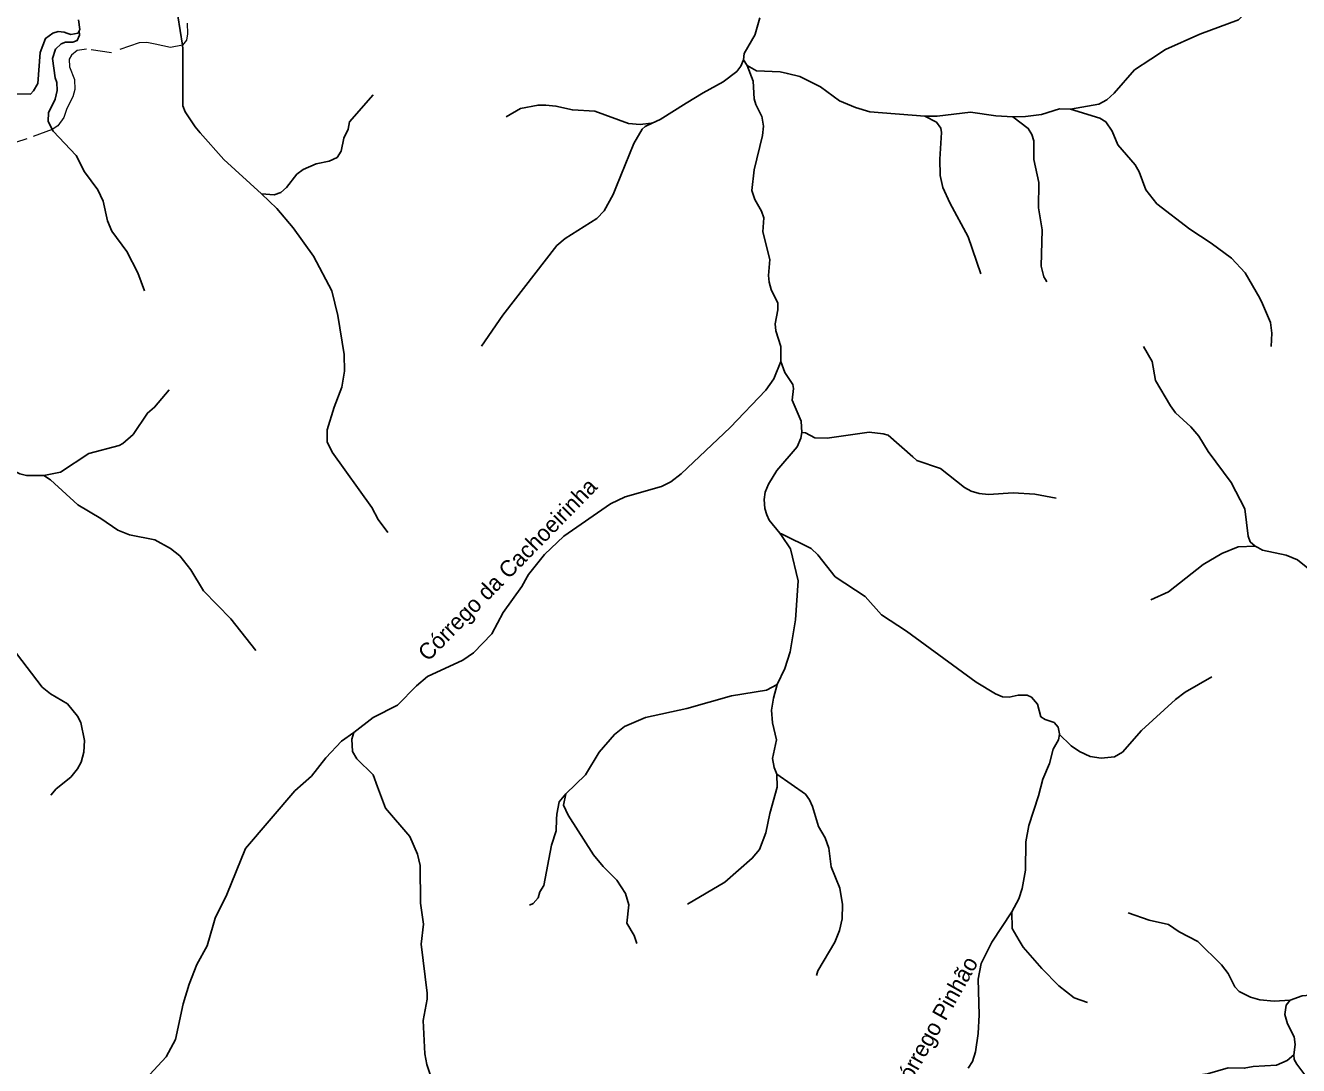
# Model space of a CAD drawing. Extents: x 473.9 to 500, y 7733.1 to 7760.8.
# Drawn here: x 481.48 to 487.72, y 7748.41 to 7753.5 of the extents above; entities that cross this region are included whole.
import ezdxf
from ezdxf.enums import TextEntityAlignment as Align

# ---------------------------------------------------------------- set-up
doc = ezdxf.new("R2010")
doc.units = 0
doc.header["$LTSCALE"] = 0.032
doc.linetypes.add('SHORT_DASHED', pattern=[2.7, 1.5, -1.2])
doc.layers.add('21', color=7, linetype='SHORT_DASHED', lineweight=13)
doc.layers.add('7', color=7, linetype='Continuous', lineweight=25)
doc.layers.add('61', color=7, linetype='Continuous')

msp = doc.modelspace()

# ---------------------------------------------------------------- linework, layer by layer
at = {"layer": '21'}
for points in [[(482.2765, 7753.5139), (482.2782, 7753.4628), (482.2731, 7753.4304), (482.2522, 7753.407)], [(482.2522, 7753.407), (482.1948, 7753.3947), (482.1184, 7753.4115), (482.078, 7753.4191), (482.0406, 7753.418), (481.9044, 7753.3699), (481.7824, 7753.3874), (481.7363, 7753.3808), (481.7091, 7753.3579), (481.6973, 7753.3383), (481.6989, 7753.2997), (481.7235, 7753.2383), (481.7251, 7753.1887), (481.7159, 7753.1539), (481.6852, 7753.0955), (481.6713, 7753.0526), (481.6415, 7753.0116), (481.6148, 7752.994)], [(481.6148, 7752.994), (481.4906, 7752.9475), (481.4339, 7752.9294), (481.3738, 7752.8971), (481.3009, 7752.8454), (481.2522, 7752.8327), (481.1964, 7752.827), (481.1559, 7752.8103), (481.1272, 7752.7832), (481.0901, 7752.6822), (481.079, 7752.6676), (481.0582, 7752.6403), (481.0361, 7752.6262), (480.9428, 7752.5927), (480.9205, 7752.577), (480.9027, 7752.5377), (480.9186, 7752.4147), (480.9083, 7752.277), (480.8936, 7752.2196), (480.8676, 7752.1741), (480.848, 7752.162), (480.7931, 7752.1553)]]:
    msp.add_lwpolyline(points, dxfattribs=at)
at = {"layer": '7'}
msp.add_line((485.0216, 7753.3077), (485.0036, 7753.3356), dxfattribs=at)
for points in [[(483.1296, 7754.8539), (483.1149, 7754.7823), (483.0796, 7754.7372), (482.9905, 7754.6958), (482.7757, 7754.5657), (482.7324, 7754.5381), (482.6795, 7754.4882), (482.5869, 7754.2753), (482.4227, 7754.0463), (482.3873, 7753.9719), (482.369, 7753.9149), (482.2405, 7753.7174), (482.2311, 7753.6852), (482.2306, 7753.551), (482.2522, 7753.407)], [(487.671, 7753.9257), (487.6551, 7753.8617), (487.6509, 7753.8037), (487.642, 7753.7843), (487.5676, 7753.7056), (487.4959, 7753.599), (487.4299, 7753.5316), (487.2405, 7753.4613), (487.0722, 7753.386), (486.9996, 7753.3382), (486.9192, 7753.2853), (486.8205, 7753.1711), (486.7836, 7753.1389), (486.7449, 7753.1182), (486.6061, 7753.0928)], [(481.7437, 7753.5302), (481.7497, 7753.4837), (481.746, 7753.4764)], [(485.0036, 7753.3356), (485.0068, 7753.3652), (485.0595, 7753.459), (485.0603, 7753.4604), (485.0828, 7753.5407)], [(481.746, 7753.4764), (481.7407, 7753.4658), (481.7054, 7753.4592), (481.6865, 7753.466), (481.6725, 7753.471), (481.6436, 7753.4739), (481.6173, 7753.466), (481.5815, 7753.44), (481.5557, 7753.3713), (481.5433, 7753.219), (481.5233, 7753.1829), (481.5076, 7753.1672), (481.4409, 7753.1674)], [(481.6148, 7752.994), (481.5947, 7753.0345), (481.5968, 7753.0748), (481.6282, 7753.1414), (481.6389, 7753.1844), (481.6374, 7753.2234), (481.629, 7753.2458), (481.6152, 7753.3414), (481.6298, 7753.3864), (481.6587, 7753.4139), (481.6798, 7753.421), (481.7096, 7753.4208), (481.7147, 7753.4208), (481.737, 7753.4298), (481.7482, 7753.4556), (481.746, 7753.4764)], [(482.2522, 7753.407), (482.255, 7753.3884), (482.2551, 7753.1095), (482.2654, 7753.0805), (482.3143, 7753.0061), (482.3401, 7752.9771), (482.4562, 7752.8464), (482.6401, 7752.6788)], [(484.5556, 7753.0242), (484.5937, 7753.0424), (484.7214, 7753.1218), (484.8049, 7753.1737), (484.9027, 7753.2266), (484.9696, 7753.2783), (484.9898, 7753.3038), (485.0036, 7753.3356)], [(485.8921, 7753.0585), (485.6228, 7753.0797), (485.5516, 7753.1004), (485.4736, 7753.1333), (485.3808, 7753.2018), (485.2787, 7753.2524), (485.2185, 7753.2671), (485.1819, 7753.2761), (485.0673, 7753.2806), (485.0216, 7753.3077)], [(485.1864, 7751.8564), (485.1863, 7751.9295), (485.1615, 7752.0074), (485.1583, 7752.0403), (485.1719, 7752.1091), (485.1719, 7752.1417), (485.1389, 7752.2101), (485.129, 7752.2452), (485.1254, 7752.2783), (485.1326, 7752.357), (485.0974, 7752.4917), (485.1029, 7752.5612), (485.0914, 7752.5937), (485.0583, 7752.6502), (485.0436, 7752.6937), (485.0557, 7752.7955), (485.0965, 7752.9634), (485.1013, 7753.009), (485.0922, 7753.0591), (485.0915, 7753.0605), (485.0639, 7753.1152), (485.0557, 7753.1443), (485.0501, 7753.2309), (485.0216, 7753.3077)], [(483.1871, 7753.1635), (483.0722, 7753.0316), (483.0649, 7752.9945), (483.0442, 7752.9514), (483.0314, 7752.8873), (483.0107, 7752.8557), (482.9726, 7752.8386), (482.9089, 7752.8246), (482.8444, 7752.7979), (482.8141, 7752.7745), (482.7632, 7752.7097), (482.7347, 7752.6846), (482.7021, 7752.6738), (482.6401, 7752.6788)], [(483.8393, 7753.0557), (483.9099, 7753.0969), (483.9961, 7753.1134), (484.034, 7753.1134), (484.0836, 7753.1085), (484.1642, 7753.0892), (484.2735, 7753.0838), (484.439, 7753.0225), (484.4961, 7753.018), (484.5511, 7753.0237), (484.5556, 7753.0242)], [(486.3227, 7753.0558), (486.2392, 7753.0597), (486.115, 7753.0789), (485.9517, 7753.0595), (485.8921, 7753.0585)], [(486.6061, 7753.0928), (486.5523, 7753.0944), (486.4633, 7753.0663), (486.3847, 7753.0564), (486.3227, 7753.0558)], [(487.59, 7751.9305), (487.5933, 7751.9947), (487.5854, 7752.0473), (487.5463, 7752.1393), (487.5346, 7752.1668), (487.4623, 7752.2902), (487.3944, 7752.3629), (487.2956, 7752.4371), (487.1902, 7752.5049), (487.0291, 7752.6289), (486.9749, 7752.6975), (486.9417, 7752.7864), (486.9233, 7752.8201), (486.8384, 7752.9179), (486.8107, 7752.9859), (486.7786, 7753.0315), (486.7492, 7753.0491), (486.6061, 7753.0928)], [(483.7182, 7751.9313), (483.8227, 7752.084), (484.0887, 7752.4254), (484.129, 7752.4596), (484.2833, 7752.5568), (484.3205, 7752.5949), (484.3644, 7752.6748), (484.3811, 7752.7163), (484.465, 7752.9255), (484.5061, 7752.9944), (484.5212, 7753.0077), (484.5556, 7753.0242)], [(486.1657, 7752.2854), (486.1041, 7752.4668), (486.0143, 7752.6344), (485.9808, 7752.7089), (485.9673, 7752.7675), (485.9656, 7752.8476), (485.9736, 7752.9792), (485.9694, 7752.9994), (485.9495, 7753.0293), (485.8921, 7753.0585)], [(486.4905, 7752.2461), (486.4838, 7752.2578), (486.4756, 7752.272), (486.462, 7752.3234), (486.4675, 7752.5016), (486.4484, 7752.61), (486.4499, 7752.7341), (486.4259, 7752.8461), (486.4256, 7752.9374), (486.4165, 7752.9692), (486.3988, 7752.9985), (486.3227, 7753.0558)], [(482.0667, 7752.2033), (482.0335, 7752.2905), (481.9807, 7752.3951), (481.9072, 7752.4949), (481.8859, 7752.5456), (481.8644, 7752.6414), (481.8387, 7752.6976), (481.7728, 7752.7867), (481.7311, 7752.8655), (481.619, 7752.9855), (481.6148, 7752.994)], [(483.2591, 7751.0192), (483.2124, 7751.0821), (483.1814, 7751.1413), (482.9869, 7751.4119), (482.9622, 7751.463), (482.9623, 7751.521), (482.9956, 7751.6334), (483.0342, 7751.73), (483.0472, 7751.8097), (483.0455, 7751.8911), (483.015, 7752.0815), (482.9845, 7752.203), (482.8958, 7752.373), (482.796, 7752.5115), (482.716, 7752.6066), (482.6401, 7752.6788)], [(486.963, 7751.9295), (487.0065, 7751.8571), (487.0222, 7751.7627), (487.0958, 7751.6394), (487.1198, 7751.6057), (487.1949, 7751.5361), (487.2343, 7751.49), (487.2805, 7751.416), (487.393, 7751.2642), (487.4602, 7751.1351), (487.4771, 7751.0004), (487.4862, 7750.9729), (487.5104, 7750.9522)], [(483.0934, 7750.0378), (483.188, 7750.1117), (483.3067, 7750.1721), (483.3997, 7750.2668), (483.4531, 7750.3121), (483.6263, 7750.3931), (483.6787, 7750.428), (483.7687, 7750.5216), (483.8242, 7750.6257), (483.9158, 7750.7531), (483.9431, 7750.8015), (483.9497, 7750.8132), (484.0282, 7750.9099), (484.1229, 7751.0007), (484.3511, 7751.1596), (484.4225, 7751.1927), (484.6007, 7751.2435), (484.6459, 7751.2662), (484.697, 7751.3067), (484.9369, 7751.5338), (485.1117, 7751.7158), (485.1518, 7751.772), (485.1864, 7751.8564)], [(485.2887, 7751.5083), (485.2849, 7751.5643), (485.2409, 7751.6675), (485.2479, 7751.7249), (485.2448, 7751.7434), (485.2062, 7751.8028), (485.1864, 7751.8564)], [(482.1875, 7751.7176), (482.1162, 7751.6325), (482.0806, 7751.6033), (482.0106, 7751.498), (481.9605, 7751.4552), (481.9418, 7751.4451), (481.7932, 7751.4064), (481.6543, 7751.3145), (481.5737, 7751.298)], [(481.5737, 7751.298), (481.4886, 7751.2985), (481.4551, 7751.3053), (481.3948, 7751.3377), (481.2571, 7751.3837), (481.1528, 7751.4504)], [(485.1816, 7751.0152), (485.1291, 7751.0796), (485.1168, 7751.1058), (485.1069, 7751.1358), (485.1047, 7751.1808), (485.1099, 7751.2156), (485.1254, 7751.2554), (485.1668, 7751.3227), (485.2666, 7751.4387), (485.2847, 7751.481), (485.2887, 7751.5083)], [(486.5351, 7751.1862), (486.4306, 7751.2059), (486.3241, 7751.2122), (486.2039, 7751.2044), (486.158, 7751.2088), (486.1186, 7751.221), (486.0865, 7751.2382), (485.9691, 7751.3325), (485.8524, 7751.3721), (485.8326, 7751.3896), (485.7125, 7751.4952), (485.6879, 7751.5027), (485.6189, 7751.5098), (485.4128, 7751.4802), (485.3532, 7751.4821), (485.3069, 7751.5068), (485.2887, 7751.5083)], [(482.6118, 7750.4397), (482.4895, 7750.5955), (482.356, 7750.7329), (482.2946, 7750.8349), (482.2394, 7750.9041), (482.1939, 7750.9396), (482.1168, 7750.9826), (481.9927, 7751.0065), (481.9361, 7751.0295), (481.853, 7751.0867), (481.7397, 7751.1535), (481.6063, 7751.2759), (481.5737, 7751.298)], [(485.1684, 7750.2729), (485.2051, 7750.3523), (485.2313, 7750.4334), (485.2444, 7750.5118), (485.2577, 7750.5909), (485.2713, 7750.7814), (485.2327, 7750.9389), (485.1892, 7751.0039), (485.1816, 7751.0152)], [(486.5526, 7750.0292), (486.5521, 7750.0316), (486.5459, 7750.0652), (486.5252, 7750.0874), (486.4823, 7750.1018), (486.4612, 7750.1156), (486.4443, 7750.178), (486.4145, 7750.2109), (486.3926, 7750.2221), (486.3486, 7750.2213), (486.3047, 7750.2118), (486.2732, 7750.2134), (486.2379, 7750.2281), (486.1434, 7750.2857), (485.8023, 7750.5346), (485.6797, 7750.6149), (485.5995, 7750.7046), (485.4528, 7750.8008), (485.3673, 7750.9088), (485.3352, 7750.9407), (485.1918, 7751.0103), (485.1816, 7751.0152)], [(486.9992, 7750.6887), (487.0868, 7750.7283), (487.256, 7750.8617), (487.3477, 7750.9156), (487.4284, 7750.9478), (487.5104, 7750.9522)], [(487.5104, 7750.9522), (487.5248, 7750.9443), (487.5467, 7750.9322), (487.6635, 7750.9078), (487.7193, 7750.8848), (487.8966, 7750.7414), (487.9591, 7750.6809), (487.9995, 7750.6532), (488.0858, 7750.6197), (488.1184, 7750.5966), (488.1518, 7750.5266), (488.1819, 7750.4843), (488.3172, 7750.3825), (488.3468, 7750.3398)], [(481.6072, 7749.7308), (481.6342, 7749.7625), (481.7055, 7749.8202), (481.738, 7749.86), (481.756, 7749.8936), (481.7691, 7749.9424), (481.7723, 7749.9987), (481.7538, 7750.0866), (481.7386, 7750.1187), (481.6887, 7750.179), (481.6054, 7750.2275), (481.5656, 7750.2604), (481.4385, 7750.4261), (481.3495, 7750.5038), (481.1301, 7750.6238), (481.024, 7750.6645), (480.9886, 7750.7029)], [(484.1326, 7749.7374), (484.2276, 7749.8304), (484.2959, 7749.9417), (484.3704, 7750.0292), (484.4199, 7750.0682), (484.5233, 7750.1121), (484.7257, 7750.1564), (484.9446, 7750.2186), (485.1154, 7750.2454), (485.1684, 7750.2729)], [(485.1668, 7749.8341), (485.1528, 7749.8669), (485.1455, 7749.9116), (485.1654, 7750.0021), (485.1451, 7750.0852), (485.1399, 7750.148), (485.1495, 7750.2072), (485.1684, 7750.2729)], [(487.2987, 7750.3105), (487.1682, 7750.236), (487.1207, 7750.1993), (486.9533, 7750.0489), (486.8608, 7749.9427), (486.8214, 7749.9193), (486.7568, 7749.9119), (486.7026, 7749.9205), (486.6502, 7749.9445), (486.6089, 7749.9738), (486.6055, 7749.9762), (486.5526, 7750.0292)], [(482.0709, 7748.3392), (482.1724, 7748.4494), (482.2191, 7748.5344), (482.2567, 7748.7095), (482.2852, 7748.8048), (482.3234, 7748.9022), (482.3735, 7748.9927), (482.4026, 7749.0943), (482.4125, 7749.1288), (482.4697, 7749.2448), (482.5611, 7749.4699), (482.8029, 7749.7518), (482.8852, 7749.8245), (482.9562, 7749.915), (483.033, 7749.996), (483.0934, 7750.0378)], [(483.4801, 7748.3227), (483.4505, 7748.4106), (483.4401, 7748.4635), (483.4321, 7748.6269), (483.4528, 7748.7313), (483.4528, 7748.7612), (483.4224, 7749.0007), (483.4337, 7749.0988), (483.4195, 7749.2017), (483.4175, 7749.3859), (483.4043, 7749.4426), (483.368, 7749.528), (483.2473, 7749.6671), (483.2087, 7749.772), (483.187, 7749.8311), (483.1067, 7749.9095), (483.086, 7749.946), (483.0826, 7750.0056), (483.0934, 7750.0378)], [(486.3188, 7749.1595), (486.3528, 7749.2236), (486.3686, 7749.274), (486.3857, 7749.3643), (486.3874, 7749.502), (486.4022, 7749.5826), (486.4493, 7749.7281), (486.4694, 7749.8099), (486.5035, 7749.8859), (486.5213, 7749.9573), (486.5478, 7750.0021), (486.5526, 7750.0292)], [(484.7292, 7749.1968), (484.9111, 7749.3048), (485.0458, 7749.4218), (485.0806, 7749.4648), (485.1126, 7749.5465), (485.1315, 7749.6414), (485.1686, 7749.7707), (485.1668, 7749.8341)], [(485.3608, 7748.8472), (485.3677, 7748.8705), (485.4502, 7749.011), (485.4738, 7749.0683), (485.4862, 7749.125), (485.4877, 7749.1951), (485.4747, 7749.2758), (485.4325, 7749.3808), (485.422, 7749.4709), (485.4027, 7749.5214), (485.3698, 7749.577), (485.3415, 7749.6762), (485.3263, 7749.7089), (485.3068, 7749.7359), (485.1668, 7749.8341)], [(483.9531, 7749.1918), (483.9716, 7749.2003), (483.9956, 7749.2287), (484.0043, 7749.2573), (484.0244, 7749.2881), (484.062, 7749.4859), (484.0849, 7749.5563), (484.087, 7749.614), (484.0879, 7749.6383), (484.0998, 7749.6986), (484.1326, 7749.7374)], [(484.4807, 7749.004), (484.4672, 7749.0435), (484.4304, 7749.1048), (484.4406, 7749.1935), (484.4245, 7749.2499), (484.3826, 7749.3148), (484.3142, 7749.3809), (484.2669, 7749.4389), (484.1428, 7749.6334), (484.12, 7749.683), (484.1326, 7749.7374)], [(486.1039, 7748.3931), (486.126, 7748.4265), (486.1396, 7748.4732), (486.1532, 7748.5626), (486.1581, 7748.6544), (486.1533, 7748.8298), (486.1684, 7748.907), (486.2202, 7749.0114), (486.3188, 7749.1595)], [(486.6886, 7748.7149), (486.6245, 7748.7387), (486.5483, 7748.7968), (486.4656, 7748.8813), (486.3745, 7748.9866), (486.3547, 7749.0198), (486.3201, 7749.0776), (486.3188, 7749.1595)], [(486.8882, 7749.1547), (486.9922, 7749.1189), (487.0865, 7749.098), (487.1384, 7749.0622), (487.2308, 7749.0139), (487.3453, 7748.9003), (487.3779, 7748.8577), (487.4116, 7748.7926), (487.4331, 7748.7699), (487.4883, 7748.7412), (487.5343, 7748.7284), (487.6039, 7748.722), (487.6827, 7748.7274)], [(487.6827, 7748.7274), (487.7421, 7748.7477), (487.8771, 7748.7589), (488.0137, 7748.7412), (488.0718, 7748.7266), (488.1481, 7748.6899), (488.1962, 7748.6804), (488.2902, 7748.7262), (488.3781, 7748.7502), (488.4114, 7748.7525), (488.5133, 7748.7282), (488.553, 7748.7268), (488.6885, 7748.7505), (488.8436, 7748.8249), (488.9213, 7748.8844), (488.9911, 7748.9732), (489.0579, 7749.0884), (489.068, 7749.1004), (489.0857, 7749.1213)], [(487.7, 7748.4595), (487.7071, 7748.5096), (487.7021, 7748.5475), (487.6689, 7748.6108), (487.6567, 7748.656), (487.6624, 7748.7015), (487.6827, 7748.7274)], [(487.0191, 7748.2502), (487.0804, 7748.2965), (487.2027, 7748.3564), (487.2773, 7748.3661), (487.3794, 7748.3957), (487.4572, 7748.3934), (487.5013, 7748.4013), (487.615, 7748.4076), (487.6676, 7748.4312), (487.7, 7748.4595)], [(487.7596, 7748.3542), (487.7145, 7748.4138), (487.7025, 7748.4363), (487.7, 7748.4595)]]:
    msp.add_lwpolyline(points, dxfattribs=at)

# ---------------------------------------------------------------- texts
at = {"layer": '61'}
for s, rotation, p in [('Córrego da Cachoeirinha', 45.616, (483.8743, 7750.8097)), ('Córrego Pinhão', 60.751, (485.9729, 7748.5846))]:
    msp.add_text(s, height=0.08, rotation=rotation, dxfattribs=at).set_placement(p, align=Align.CENTER)

doc.saveas('drawing.dxf')
